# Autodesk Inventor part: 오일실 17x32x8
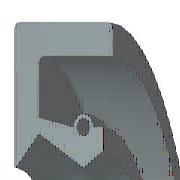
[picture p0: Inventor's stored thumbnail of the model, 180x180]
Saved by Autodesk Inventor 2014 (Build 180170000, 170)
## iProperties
IsCustomPart: 1
Company: 한국ATC센터
Created: 2014-07
Part Number: 오일실 17x32x8
Material: 고무
Description: 오일-실
Document SubType Name: Modeling
Standard: KS B 2804
Designer: KYOUNG IL JANG
Standards Organization: KS
Language: ko-KR
Size Designation: D - 17 32 8
Categories: <MemberInstance><Categories><Category DisplayName="샤프트 부품" InternalName="7f7aeb1f-a693-4053-b835-cee3144e0d98" Mnemonic="SHFT"><Category DisplayName="실링" Intern
Density: 0.93 g/cm^3
Appearance: 고무 - 검은색 - 버전 1.1
Author: KYOUNG IL JANG
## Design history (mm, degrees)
revolve "본체" stored, may be unused: angle "d17" = 90 deg
revolve "스프링1" stored, may be unused: angle "d18" = 90 deg
body "Solid1"
sketch "스케치1"
  geometry: L1 (0, 16)-(8, 16); L2 (8, 14.25)-(1.75, 14.25); L3 (1.75, 10.25)-(4.9, 8.5); L4 (4.9, 8.5)-(0, 8.5); L5 (0, 0)-(9.586, 0) reference; L6 (4.9, 8.5)-(6.3, 9.375); L7 (0, 18)-(0, -3) reference; L8 (-1.941, 0)-(11.507, 0) reference; L9 (4.2, 10.6)-(1.75, 11.21); L10 (1.75, 11.21)-(1.75, 14.25); L11 (0, 16)-(0, 8.588); L12 (4.9, 8.5)-(0, 8.5); L13 (1.75, 10.25)-(0.152, 8.528); L14 (8, 16)-(8, 14.25); L15 (5.6, 10.6)-(6.3, 10.6); L16 (6.3, 10.6)-(6.3, 9.375); C1 r 0.455 at (4.9, 10.6); A1 r 0.7 centre (4.9, 10.6) between (5.6, 10.6) and (4.2, 10.6); A2 r 0.088 centre (0.088, 8.588) between (0, 8.588) and (0.152, 8.528); 1 further point
  constraints: 28 end point, 5 horizontal alignment, 5 point on line, 4 point on circle, 4 vertical alignment, 3 centre point, 3 tangent, 2 collinear, 2 horizontal, 2 perpendicular, 1 coincident, 1 parallel
  dimensions: "d0" = 32 diameter of L1 L5 (= SD2); "d1" = 1.75 distance of L1.end L2.start (= SD); "d2" = 0.91 diameter of C1 (= SPDI); "d3" = 1.4 diameter of A1 (= SPDA); "d4" = 17 diameter of L3.end L5 (= NND); "d5" = 20.5 diameter of L3.start L5 (= TKDM); "d7" = 22.42 diameter of L9.end L5 (= TKDM + 0.24 x SWDT); "d8" = 1.75 distance between parallel lines of L11 L10 (= SD); "d9" = 4.9 distance from line of L11 C1.centre (= SPDST); "d10" = 21.2 diameter of C1.centre L5 (= HLDM); "d11" = 0.0875 radius of A2 (= 0.25 x LAB); "d12" = 6.3 distance between parallel lines of L11 L16 (= SDI); "d13" = 18.75 diameter of L6.end L5 (= ABDM); "d14" = 8 distance from line of L11 L1.end (= SWDT)
fillet "모깎기1" dims "d6" = 0.3 (= RR)
other parameters: "SD2" = 32 [user parameter; used in 1 equation term], "SWDT" = 8 [user parameter; used in 2 equation terms], "RR" = 0.3 [user parameter; used in 1 equation term], "SD" = 1.75 [user parameter; used in 2 equation terms], "NND" = 17 [user parameter; used in 1 equation term], "SPDA" = 1.4 [user parameter; used in 1 equation term], "SPDI" = 0.91 [user parameter; used in 1 equation term], "TKDM" = 20.5 [user parameter; used in 2 equation terms], "HLDM" = 21.2 [user parameter; used in 1 equation term], "ABDM" = 18.75 [user parameter; used in 1 equation term], "SDI" = 6.3 [user parameter; used in 1 equation term], "SPDST" = 4.9 [user parameter; used in 1 equation term], "LAB" = 0.35 [user parameter; used in 1 equation term], "d15" = 0, "d16" = 0, "d19" = 0
